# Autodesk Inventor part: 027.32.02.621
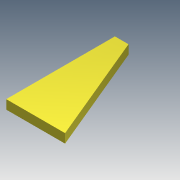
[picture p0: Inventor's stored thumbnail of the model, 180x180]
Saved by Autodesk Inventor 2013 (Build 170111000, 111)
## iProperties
Created: 2005-04
Part Number: 027.32.02.621
Material: Steel, Mild
Document SubType Name: Modeling
Designer: salex
Manufacturer: Standard
Standards Organization: Custom
Density: 7.86 g/cm^3
Author: salex
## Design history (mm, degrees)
sketch "Эскиз1"
  geometry: L1 (0, 0)-(65, 0); L2 (65, 0)-(15, 120); L3 (15, 120)-(0, 120); L4 (0, 120)-(0, 0)
  constraints: 8 end point, 1 horizontal, 1 parallel, 1 perpendicular, 1 other
  dimensions: "d0" = 65 distance of L1.start L1.end; "d1" = 120 distance of L3.end L1.start; "d2" = 15 distance of L2.end L3.end
extrude "Выдавливание1" new body sketch "Эскиз1" distance "d3" = 10; taper "d4" = 0 deg
body "Solid1"
